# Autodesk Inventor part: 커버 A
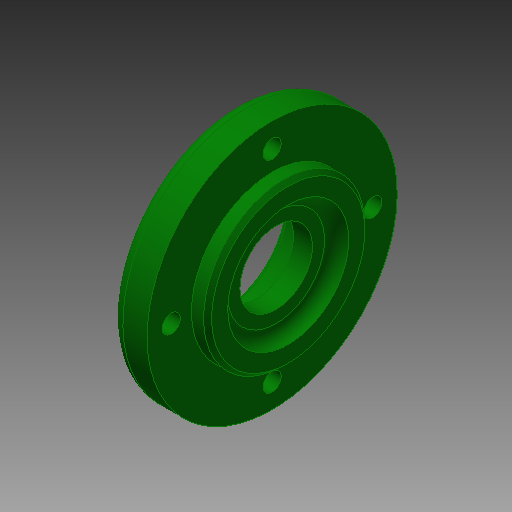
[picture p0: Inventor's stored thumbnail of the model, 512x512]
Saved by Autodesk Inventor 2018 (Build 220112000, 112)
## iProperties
Created: 2019-01
Part Number: 커버 A
Material: 알루미늄 6061
Document SubType Name: Modeling
Designer: mduedu
Density: 2.71 g/cm^3
Appearance: 진녹색
Mass: 67.6019 g
Surface Area: 94.4617 cm^2
Volume: 24.9453 cm^3
Author: mduedu
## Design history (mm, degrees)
sketch "스케치1"
  geometry: L1 (0, 0)-(9, 0); L2 (9, 0)-(9, 31); L3 (9, 31)-(0, 31); L4 (0, 31)-(0, 0); L5 (9, 0)-(13, 0); L6 (13, 0)-(13, 20); L7 (13, 20)-(9, 20); L8 (9, 20)-(9, 0)
  constraints: 16 end point, 4 parallel, 2 horizontal, 2 perpendicular
  dimensions: "d0" = 13 distance between parallel lines of L6 L4; "d2" = 62 diameter of L3 L1; "d3" = 40 diameter of L7 L5; "d4" = 4 distance between parallel lines of L6 L2
revolve "회전1" sketch "스케치1" stored, may be unused: angle "d5" = 90 deg
sketch "스케치5"
  geometry: C1 r 19 at (0, 0); 1 further point
  constraints: 1 centre point, 1 coincident
  dimensions: "d34" = 38 diameter of C1
extrude "돌출1" join sketch "스케치5" distance "d35" = 3; taper "d36" = 0 deg
sketch "스케치2"
  geometry: L1 (9, -20)-(9, -31) reference; L2 (9, -31)-(0, -31) reference; L3 (0, -31)-(0, -19) reference; L4 (0, -19)-(-3, -19) reference; L5 (-3, -19)-(-3, 19) reference; L6 (-3, 19)-(0, 19) reference; L7 (0, 19)-(0, 31) reference; L8 (0, 31)-(9, 31) reference; L9 (9, 31)-(9, 20) reference; L10 (9, 20)-(13, 20) reference; L11 (13, 20)-(13, -20) reference; L12 (13, -20)-(9, -20) reference; L13 (-3, 0)-(5.3, 0); L14 (5.3, 0)-(5.3, 15); L15 (5.3, 15)-(-3, 15); L16 (-3, 15)-(-3, 0); L17 (5.3, 0)-(10, 0); L18 (10, 0)-(10, 9); L19 (10, 9)-(5.3, 9); L20 (5.3, 9)-(5.3, 0); L21 (10, 0)-(13, 0); L22 (13, 0)-(13, 15); L23 (13, 15)-(10, 15); L24 (10, 15)-(10, 0)
  constraints: 24 end point, 6 parallel, 3 horizontal, 3 perpendicular, 1 midpoint, 1 point on line
  dimensions: "d38" = 30 diameter of L15 L13; "d40" = 30 diameter of L23 L21; "d41" = 3 distance of L22.end L23.end; "d42" = 8.3 distance of L14.end L15.end; "d43" = 18 diameter of L19 L17
revolve "회전2" sketch "스케치2" stored, may be unused: angle "d12" = 90 deg
chamfer "모따기1" distance "d13" = 0.8; stored, may be unused: second distance "d14" = 2, angle "d15" = 30 deg
fillet "모깎기1" dims "d16" = 0.5
fillet "모깎기2" dims "d17" = 3
fillet "모깎기3" dims "d18" = 3
chamfer "모따기2" distance "d24" = 1; stored, may be unused: second distance "d25" = 2, angle "d26" = 45 deg
sketch "스케치3" dims "d19" = 50
  geometry: 6 further points
  constraints: 2 vertical alignment, 1 coincident, 7 other
  dimensions: "d22" = 360 deg dimension on point (0, 0) point (0, 25) (derived)
sketch "스케치4"
  geometry: 4 further points
  constraints: 4 other
hole "구멍1" sketch "스케치4" at (-25, 0), (0, -25), (25, 0), (0, 25) diameter "d27" = 4.5; stored, may be unused: countersink angle "d31" = 90 deg, drill point angle "d33" = 0 deg; dims "d28" = 6, "d29" = 8, "d30" = 4.6, "d32" = 8
fillet "모깎기6" dims "d47" = 1
node "솔리드1"
node "절단 모서리 투영2"
